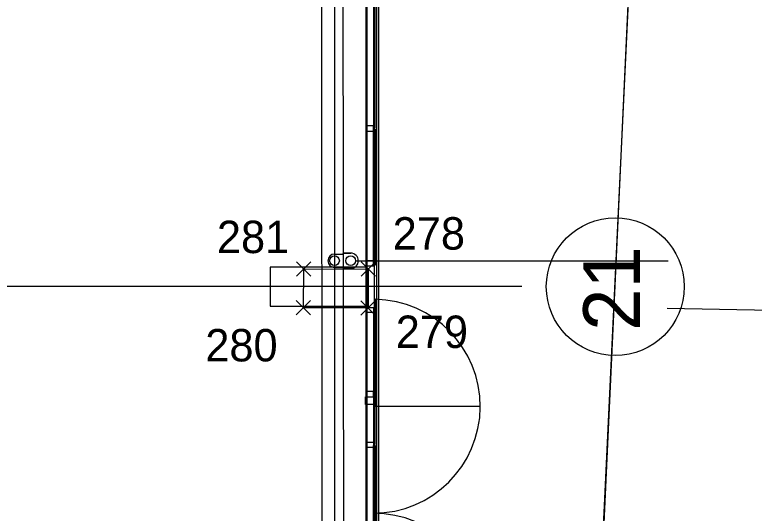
# Model space of a CAD drawing. Extents: x -264205 to -263659, y -1242401 to -1242060.
# Drawn here: x -263800.48 to -263789.07, y -1242220.38 to -1242212.69 of the extents above; entities that cross this region are included whole.
import ezdxf

# ---------------------------------------------------------------- set-up
doc = ezdxf.new("R2010")
doc.units = 0
for name, color, linetype in [('BOD_CISLO', 7, 'Continuous'), ('BOD_SYMBOL', 7, 'Continuous'), ('KFA_SO_10-1_BETONOVE_STLPY', 7, 'Continuous'), ('KFA_SO_10-1_PLACHTY', 7, 'Continuous'), ('KFA_SO_10-1_STRECHY', 7, 'Continuous'), ('KFA_SO_10-1_TRIBUNA_C_OBVOD', 7, 'Continuous'), ('OBRUBNIKY_KOMUNIKACIE_PROJEKT', 7, 'Continuous'), ('OSI_STAVBY_KFA', 7, 'Continuous'), ('SITUACIA_DSP_2D', 7, 'Continuous')]:
    doc.layers.add(name, color=color, linetype=linetype)

msp = doc.modelspace()

# ---------------------------------------------------------------- linework, layer by layer
at = {"layer": 'BOD_SYMBOL'}
for p, q in [((-263796.128, -1242216.72), (-263795.907, -1242216.498)), ((-263795.907, -1242216.72), (-263796.128, -1242216.498)), ((-263795.133, -1242216.721), (-263794.912, -1242216.501)), ((-263794.912, -1242216.721), (-263795.133, -1242216.501)), ((-263796.134, -1242217.319), (-263795.913, -1242217.097)), ((-263795.913, -1242217.319), (-263796.134, -1242217.097)), ((-263795.137, -1242217.322), (-263794.916, -1242217.1)), ((-263794.916, -1242217.322), (-263795.137, -1242217.1))]:
    msp.add_line(p, q, dxfattribs=at)
at = {"layer": 'KFA_SO_10-1_BETONOVE_STLPY'}
msp.add_lwpolyline([(-263795.023, -1242216.611), (-263795.026, -1242217.211), (-263796.024, -1242217.208), (-263796.018, -1242216.609)], close=True, dxfattribs=at)
at = {"layer": 'KFA_SO_10-1_PLACHTY'}
for p, q in [((-263794.856, -1242227.181), (-263794.865, -1242196.184)), ((-263790.262, -1242196.192), (-263791.751, -1242228.358))]:
    msp.add_line(p, q, dxfattribs=at)
for points in [[(-263795.396, -1242226.823), (-263795.427, -1242195.892), (-263795.456, -1242167.905), (-263795.427, -1242160.909), (-263795.402, -1242132.887), (-263795.428, -1242101.98)], [(-263794.927, -1242226.983), (-263794.921, -1242199.7), (-263794.865, -1242196.184)], [(-263791.76, -1242228.35), (-263790.229, -1242196.189)]]:
    msp.add_lwpolyline(points, dxfattribs=at)
at = {"layer": 'KFA_SO_10-1_STRECHY'}
msp.add_line((-263795.734, -1242227.196), (-263795.754, -1242101.588), dxfattribs=at)
at = {"layer": 'KFA_SO_10-1_TRIBUNA_C_OBVOD'}
msp.add_lwpolyline([(-263795.284, -1242101.267), (-263795.051, -1242101.819), (-263795.059, -1242226.991), (-263795.286, -1242227.548)], dxfattribs=at)
at = {"layer": 'OBRUBNIKY_KOMUNIKACIE_PROJEKT'}
msp.add_line((-263794.893, -1242101.382), (-263794.893, -1242227.382), dxfattribs=at)
at = {"layer": 'OSI_STAVBY_KFA'}
for p, q in [((-263795.543, -1242083.237), (-263795.543, -1242246.707)), ((-263792.653, -1242216.882), (-263911.523, -1242216.882)), ((-263792.653, -1242216.882), (-263792.653, -1242216.882))]:
    msp.add_line(p, q, dxfattribs=at)
msp.add_circle((-263791.21, -1242216.882), 1.064, dxfattribs=at)
at = {"layer": 'SITUACIA_DSP_2D'}
for p, q in [((-263794.893, -1242101.382), (-263794.893, -1242227.382)), ((-263795.043, -1242101.769), (-263795.043, -1242226.995)), ((-263794.943, -1242212.332), (-263794.943, -1242214.432)), ((-263794.918, -1242214.432), (-263794.918, -1242212.332)), ((-263794.943, -1242214.402), (-263795.043, -1242214.402)), ((-263795.043, -1242214.402), (-263795.043, -1242214.482)), ((-263794.943, -1242214.442), (-263794.943, -1242214.402)), ((-263794.943, -1242214.432), (-263794.918, -1242214.432)), ((-263794.943, -1242214.482), (-263794.943, -1242214.442)), ((-263794.943, -1242216.552), (-263794.943, -1242214.452)), ((-263794.943, -1242214.452), (-263794.918, -1242214.452)), ((-263794.918, -1242214.452), (-263794.918, -1242216.552)), ((-263795.043, -1242214.482), (-263794.943, -1242214.482)), ((-263795.543, -1242216.379), (-263795.418, -1242216.379)), ((-263795.418, -1242216.379), (-263795.404, -1242216.365)), ((-263795.293, -1242216.365), (-263795.404, -1242216.365)), ((-263795.404, -1242216.365), (-263795.293, -1242216.365)), ((-263795.218, -1242216.482), (-263790.395, -1242216.482)), ((-263794.943, -1242216.482), (-263795.043, -1242216.482)), ((-263795.043, -1242216.482), (-263795.043, -1242216.562)), ((-263794.943, -1242216.522), (-263794.943, -1242216.482)), ((-263795.038, -1242216.582), (-263796.538, -1242216.582)), ((-263796.538, -1242216.582), (-263796.538, -1242217.182)), ((-263795.543, -1242216.585), (-263795.418, -1242216.585)), ((-263795.418, -1242216.585), (-263795.404, -1242216.599)), ((-263795.404, -1242216.599), (-263795.293, -1242216.599)), ((-263795.043, -1242216.562), (-263794.943, -1242216.562)), ((-263795.038, -1242217.182), (-263795.038, -1242216.582)), ((-263794.943, -1242216.562), (-263794.943, -1242216.522)), ((-263794.918, -1242216.552), (-263794.943, -1242216.552)), ((-263794.918, -1242217.077), (-263794.918, -1242218.727)), ((-263796.538, -1242217.182), (-263795.038, -1242217.182)), ((-263795.043, -1242217.282), (-263795.043, -1242217.202)), ((-263795.043, -1242217.202), (-263794.943, -1242217.202)), ((-263795.043, -1242217.282), (-263795.043, -1242217.202)), ((-263795.043, -1242217.202), (-263794.943, -1242217.202)), ((-263794.943, -1242217.282), (-263795.043, -1242217.282)), ((-263794.943, -1242217.282), (-263795.043, -1242217.282)), ((-263794.943, -1242217.202), (-263794.943, -1242217.242)), ((-263794.943, -1242217.202), (-263794.943, -1242217.242)), ((-263794.918, -1242217.212), (-263794.943, -1242217.212)), ((-263794.943, -1242217.212), (-263794.943, -1242219.312)), ((-263794.943, -1242217.242), (-263794.943, -1242217.282)), ((-263794.918, -1242217.242), (-263794.943, -1242217.242)), ((-263794.943, -1242217.242), (-263794.943, -1242218.542)), ((-263794.943, -1242217.242), (-263794.943, -1242217.282)), ((-263794.918, -1242219.312), (-263794.918, -1242217.212)), ((-263794.918, -1242218.542), (-263794.918, -1242217.242)), ((-263781.818, -1242217.375), (-263790.409, -1242217.218)), ((-263794.943, -1242218.502), (-263795.043, -1242218.502)), ((-263795.043, -1242218.502), (-263795.043, -1242218.582)), ((-263794.943, -1242218.542), (-263794.943, -1242218.502)), ((-263794.943, -1242218.542), (-263794.918, -1242218.542)), ((-263794.943, -1242218.582), (-263794.943, -1242218.542)), ((-263795.063, -1242218.702), (-263795.063, -1242218.582)), ((-263795.063, -1242218.582), (-263794.943, -1242218.582)), ((-263795.043, -1242218.582), (-263794.943, -1242218.582)), ((-263794.943, -1242218.582), (-263794.943, -1242218.702)), ((-263794.943, -1242218.702), (-263795.063, -1242218.702)), ((-263794.943, -1242218.702), (-263794.943, -1242218.727)), ((-263794.943, -1242218.727), (-263793.293, -1242218.727)), ((-263795.043, -1242219.362), (-263795.043, -1242219.282)), ((-263795.043, -1242219.282), (-263794.943, -1242219.282)), ((-263794.943, -1242219.282), (-263794.943, -1242219.322)), ((-263794.943, -1242219.312), (-263794.918, -1242219.312)), ((-263794.943, -1242219.322), (-263794.943, -1242219.362)), ((-263794.943, -1242221.432), (-263794.943, -1242219.332)), ((-263794.943, -1242219.332), (-263794.918, -1242219.332)), ((-263794.918, -1242219.332), (-263794.918, -1242221.432)), ((-263794.943, -1242219.362), (-263795.043, -1242219.362))]:
    msp.add_line(p, q, dxfattribs=at)
for centre in [(-263795.543, -1242216.482), (-263795.293, -1242216.482)]:
    msp.add_circle(centre, 0.075, dxfattribs=at)
for centre, radius, start, end in [((-263795.543, -1242216.482), 0.103, 90, 270), ((-263795.293, -1242216.482), 0.117, 270, 90), ((-263794.943, -1242218.727), 1.65, 270, 89.1318), ((-263794.943, -1242222.027), 1.65, 270.8682, 90)]:
    msp.add_arc(centre, radius, start, end, dxfattribs=at)

# ---------------------------------------------------------------- texts
at = {"layer": 'BOD_CISLO'}
for s, p in [('278', (-263794.645, -1242216.31)), ('281', (-263797.358, -1242216.364)), ('279', (-263794.598, -1242217.828)), ('280', (-263797.537, -1242218.035))]:
    msp.add_text(s, height=0.5, dxfattribs=at).set_placement(p)
at = {"layer": 'OSI_STAVBY_KFA'}
msp.add_text('21', height=0.875, rotation=90, dxfattribs=at).set_placement((-263790.829, -1242217.562))

doc.saveas('drawing.dxf')
